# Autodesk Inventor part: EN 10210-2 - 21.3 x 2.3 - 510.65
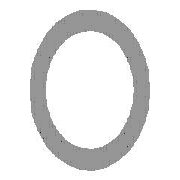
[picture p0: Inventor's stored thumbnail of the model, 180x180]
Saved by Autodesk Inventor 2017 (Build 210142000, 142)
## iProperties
Created: 2016-02
Part Number: EN 10210-2 - 21.3 x 2.3 - 510.65
Material: Steel, Mild
Description: Pipe
Document SubType Name: Modeling
Standard: DIN
Designer: iusti
Standard Revision: 2006-07
Standards Organization: DIN
Language: en-US
Size Designation: 21.3 x 2.3
Categories: <MemberInstance><Categories><Category DisplayName="Structural Shapes" InternalName="089c4875-fa83-4c05-b084-43b9cc11f5ed" Mnemonic="GRDR"><CategoryParameter Dis
Stock Number: 21.3 x 2.3
Density: 7.85 g/cm^3
Appearance: Semi-Polished
_CCFamilyMember: 1
_CCFamilyDisplayName: DIN EN 10210-2 - Pipe
_FrameMemberDoc: Frame Member File
_Version: 15.0.0
_GetPNFromCC: 1
IsCustomPart: 1
Author: iusti
G_L: 510.650 mm
G_W: 21.300 mm
G_H: 21.300 mm
+AA30E1D5-0686-4E1F-BB21-01C88EDD7D39+CUTDETAIL1: Miter 45.00 deg
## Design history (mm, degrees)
node "Start plane"
node "End plane"
sketch "Sketch"
  geometry: C1 r 8.35 at (0, 0); C2 r 10.65 at (0, 0); 2 further points
  constraints: 3 coincident, 2 centre point
  dimensions: "d0" = 21.3 diameter of C2 (= G_H); "d1" = 2.3 radial gap between concentric circles of C2 C1 (= G_T)
extrude "Body" new body sketch "Sketch" stored distance "d2" = 510.65 (= G_L); taper "d3" = 0 deg
node "Driven Length"
  sketch "Sketch3"
    geometry: L1 (0, 0)-(10, 0) reference
    constraints: 2 end point, 1 horizontal
  workplane "Work Plane3"
  sketch "Sketch4"
    geometry: L1 (-2, 0)-(12, 0) reference; L2 (-2, 510.65)-(12, 510.65) reference
    dimensions: "d7" = 510.65 distance between parallel lines of L1 L2 (derived)
workplane "Work Plane4"
split "Split1"
body "Solid1"
other parameters: "G_H" = 21.3 [user parameter; used in 1 equation term], "G_T" = 2.3 [user parameter; used in 1 equation term], "G_L" = 510.65 (= d7) [user parameter; used in 1 equation term], "G_OFFSET_START" = 0 [user parameter; used in 1 equation term], "G_OFFSET_END" = 10.65 [user parameter; used in 1 equation term], "d4" = 0 (computed from G_OFFSET_START), "d5" = 510.65 (= G_OFFSET_END + B_L), "d6" = 90 deg
